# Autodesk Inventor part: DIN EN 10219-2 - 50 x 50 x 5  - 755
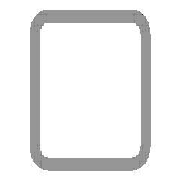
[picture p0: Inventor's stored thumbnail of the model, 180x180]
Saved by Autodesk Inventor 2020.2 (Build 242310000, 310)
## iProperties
Created: 2019-10
Part Number: DIN EN 10219-2 - 50 x 50 x 5  - 755
Material: Stahl, weich
Description: Kaltgeformte, geschweißte Baustahl-Hohlprofile aus unlegiertem Feinkorn-Baustahl
Document SubType Name: Modeling
Standard: DIN
Designer: lutzd
Standard Revision: 2006-07
Standards Organization: DIN
Language: de-DE
Size Designation: 50 x 50 x 5
Categories: <MemberInstance><Categories><Category DisplayName="Profile" InternalName="089c4875-fa83-4c05-b084-43b9cc11f5ed" Mnemonic="GRDR"><CategoryParameter DisplayName="
Stock Number: 50 x 50 x 5
Mass: 4947.06 g
Surface Area: 2541.68 cm^2
Volume: 630.199 cm^3
Density: 7.85 g/cm^3
Appearance: Semi-Polished(8)
IsCustomPart: 1
G_L: 755,000 mm
G_W: 50,000 mm
G_H: 50,000 mm
Mass: 4,947 kg
VLT_Material: Stahl, weich
DocNumber: ADSK-014380
Folder: .
+C7160FA8-47E9-4F34-A9BE-EE44514F4FA3+SCHNITTDETAIL1: Schnittwinkel 90,00 grd
+9E9D0D38-1434-4DB6-A839-0677EE423B33+SCHNITTDETAIL2: Schnittwinkel 90,00 grd
Dimensions: 50x50x755 mm
_CCFamilyMember: 16
_CCFamilyDisplayName: DIN EN 10219-2 (Quadratisches Hohlprofil - Kaltgeformt) - Kaltgeformte, geschweißte Baustahl-Hohlprofile aus unlegiertem Feinkorn-Baustahl
_FrameMemberDoc: Frame Member File
_Version: 15.0.0
_GetPNFromCC: 1
Title: Profil-Bauteil
Author: lutzd
Revision Number: -
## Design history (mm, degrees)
node "Startebene"
node "Endebene"
sketch "Skizze"
  geometry: L1 (-25, -15)-(-25, 15); L2 (-15, 25)-(15, 25); L3 (25, 15)-(25, -15); L4 (15, -25)-(-15, -25); L5 (-15, 20)-(15, 20); L6 (20, 15)-(20, -15); L7 (15, -20)-(-15, -20); L8 (-20, -15)-(-20, 15); L9 (0, 37.899)-(0, -37.899) reference; L10 (-37.899, 0)-(37.899, 0) reference; A1 r 10 centre (-15, -15) between (-25, -15) and (-15, -25); A2 r 10 centre (-15, 15) between (-15, 25) and (-25, 15); A3 r 10 centre (15, 15) between (25, 15) and (15, 25); A4 r 10 centre (15, -15) between (15, -25) and (25, -15); A5 r 5 centre (-15, 15) between (-15, 20) and (-20, 15); A6 r 5 centre (15, 15) between (20, 15) and (15, 20); A7 r 5 centre (15, -15) between (15, -20) and (20, -15); A8 r 5 centre (-15, -15) between (-20, -15) and (-15, -20)
  constraints: 16 end point, 16 point on circle, 8 centre point, 8 tangent, 4 parallel, 3 equal radius, 2 perpendicular, 7 other
  dimensions: "d7" = 10 radius of A1 (= G_IR); "d10" = 50 distance between parallel lines of L2 L4 (= G_H); "d11" = 50 distance between parallel lines of L1 L3 (= G_W); "d12" = 5 distance between parallel lines of L3 L6 (= G_T); "d15" = 25 distance between parallel lines of L2 L10 (= 0.5 x d10); "d16" = 25 distance between parallel lines of L9 L3 (= 0.5 x d11)
extrude "Körper" new body sketch "Skizze" stored distance "d3" = 755 (= G_L); taper "d4" = 0 deg
node "Driven Length"
  sketch "Sketch3"
    geometry: L1 (0, 0)-(10, 0) reference
    constraints: 2 end point, 1 horizontal
  workplane "Work Plane3"
  sketch "Sketch4"
    geometry: L1 (-2, 25)-(12, 25) reference; L2 (-2, 780)-(12, 780) reference
    dimensions: "d18" = 755 distance between parallel lines of L1 L2 (derived)
workplane "Arbeitsebene4"
feature "Trennen1"
workplane "Arbeitsebene5"
feature "Trennen2"
sketch "Skizze5"
  geometry: L1 (30, 0)-(0, 0) reference; L2 (15, 0)-(15, 321); 5 further points
  constraints: 3 point on line, 2 end point, 1 coincident, 1 midpoint, 1 vertical
  dimensions: "d19" = 52 distance of point (15, 269) point (15, 321); "d20" = 52 distance of point (15, 110) point (15, 162) (= d19); "d21" = 159 distance of point (15, 269) point (15, 110); "d22" = 110 distance from line of L1 point (15, 110)
hole "Bohrung1" sketch "Skizze5" at (15, 321), (15, 269), (15, 110), (15, 162) diameter "d23" = 6.647; stored, may be unused: countersink angle "d27" = 90 deg, drill point angle "d29" = 118 deg; dims "d24" = 16, "d25" = 4, "d26" = 2, "d28" = 8
body "Solid1"
other parameters: "G_W" = 50 [user parameter; used in 1 equation term], "G_H" = 50 [user parameter; used in 1 equation term], "G_T" = 5 [user parameter; used in 1 equation term], "G_IR" = 10 [user parameter; used in 1 equation term], "G_L" = 755 (= d18) [user parameter; used in 1 equation term], "G_OFFSET_START" = -25 [user parameter; used in 1 equation term], "G_OFFSET_END" = -25 [user parameter; used in 1 equation term], "d13" = 25 (= -G_OFFSET_START), "B_L" = 805 [user parameter; used in 1 equation term], "d17" = 90 deg
